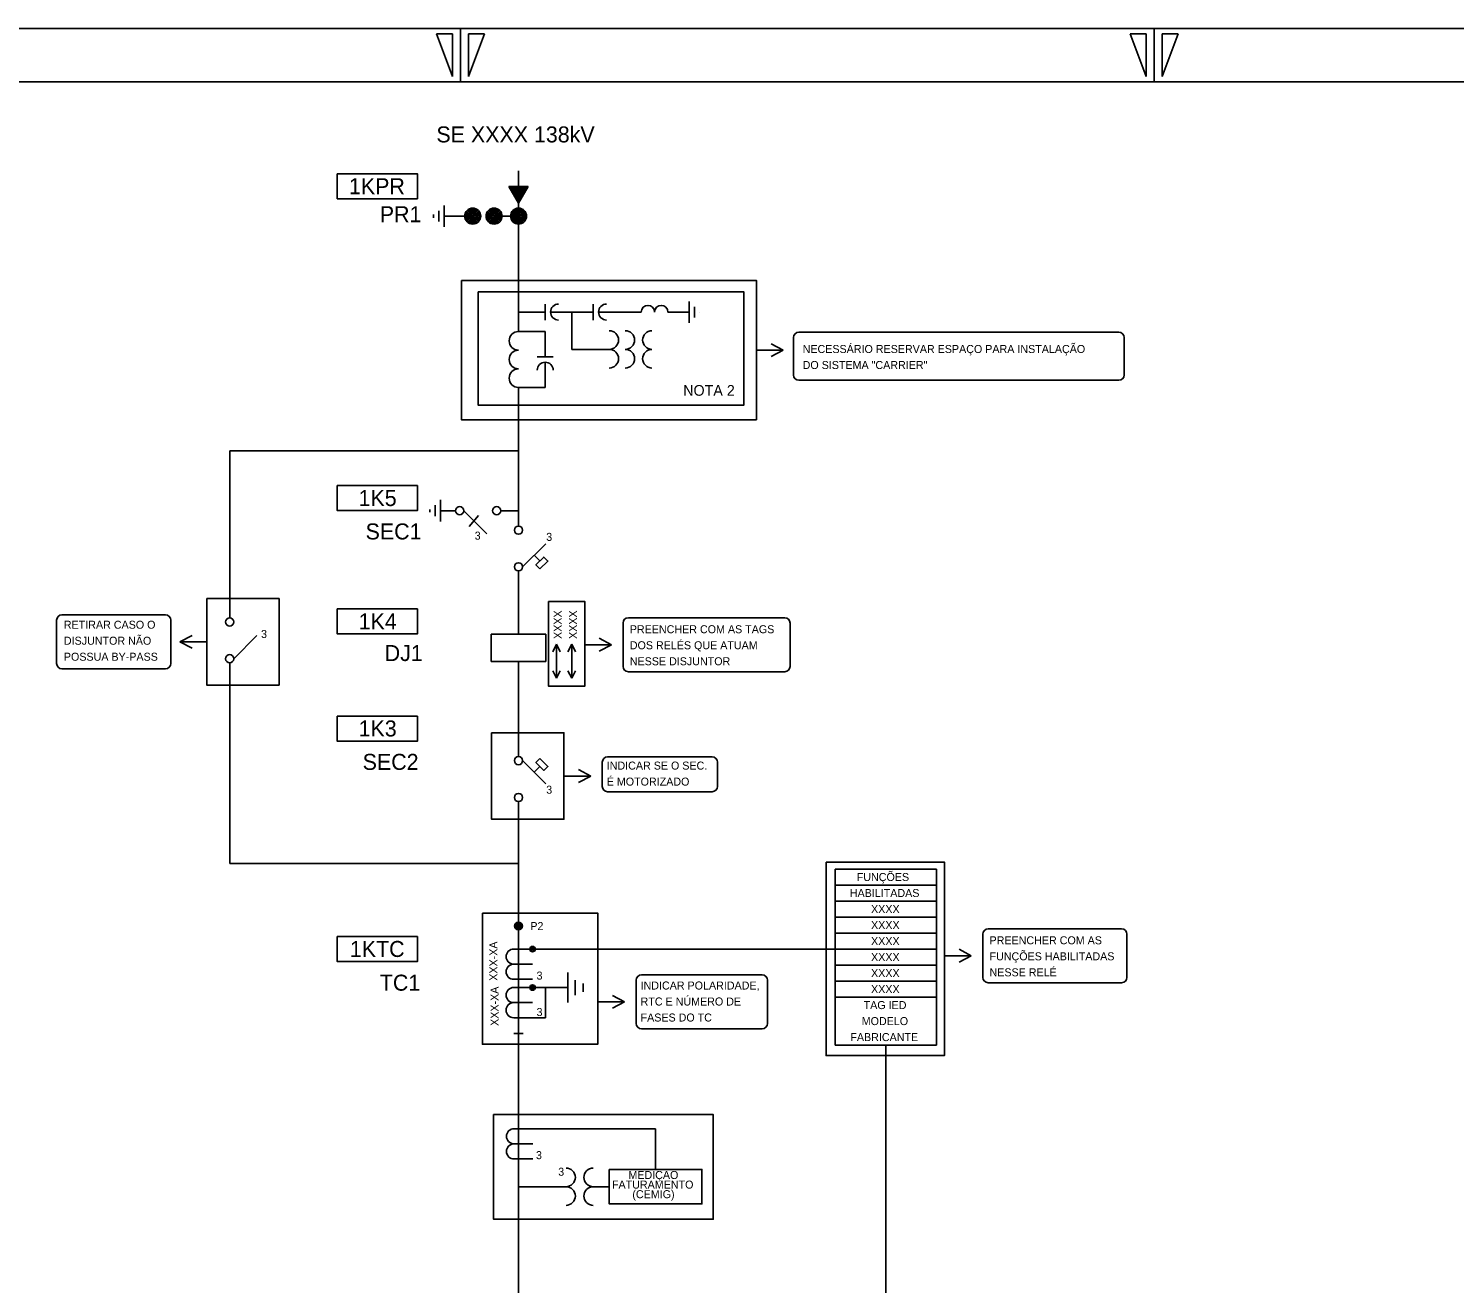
# Model space of a CAD drawing. Extents: x 563 to 1404, y 358 to 952.
# Drawn here: x 822.6 to 1089.8, y 716.8 to 952 of the extents above; entities that cross this region are included whole.
import ezdxf

# ---------------------------------------------------------------- set-up
doc = ezdxf.new("R2010")
doc.units = 0
doc.layers.add('Level 1', color=7, linetype='Continuous')
doc.layers.add('New Level (0)', color=7, linetype='Continuous')

msp = doc.modelspace()

# ---------------------------------------------------------------- linework, layer by layer
for p, q in [((914.46, 925.28), (914.46, 895.18)), ((916.27, 922.35), (912.65, 922.35)), ((912.65, 922.35), (914.46, 919.25)), ((916.27, 922.35), (912.65, 922.35)), ((916.08, 922.25), (912.83, 922.25)), ((912.83, 922.25), (914.46, 919.46)), ((915.9, 922.14), (913.01, 922.14)), ((913.01, 922.14), (914.46, 919.67)), ((915.72, 922.04), (913.19, 922.04)), ((913.19, 922.04), (914.46, 919.87)), ((915.54, 921.94), (913.37, 921.94)), ((913.37, 921.94), (914.46, 920.08)), ((914.46, 919.25), (916.27, 922.35)), ((914.46, 922.35), (914.46, 919.25)), ((914.46, 919.46), (916.08, 922.25)), ((914.46, 919.67), (915.9, 922.14)), ((914.46, 919.87), (915.72, 922.04)), ((914.46, 920.08), (915.54, 921.94)), ((915.36, 921.83), (913.55, 921.83)), ((913.55, 921.83), (914.46, 920.29)), ((915.18, 921.73), (913.73, 921.73)), ((913.73, 921.73), (914.46, 920.49)), ((915, 921.63), (913.91, 921.63)), ((913.91, 921.63), (914.46, 920.7)), ((914.82, 921.52), (914.09, 921.52)), ((914.09, 921.52), (914.46, 920.9)), ((914.64, 921.42), (914.27, 921.42)), ((914.27, 921.42), (914.46, 921.11)), ((914.46, 920.29), (915.36, 921.83)), ((914.46, 920.49), (915.18, 921.73)), ((914.46, 920.7), (915, 921.63)), ((914.46, 920.9), (914.82, 921.52)), ((914.46, 921.11), (914.64, 921.42)), ((898.55, 917.1), (898.55, 916.5)), ((898.55, 916.8), (898.55, 916.8)), ((899.55, 917.8), (899.55, 915.8)), ((900.55, 914.8), (900.55, 918.8)), ((901.87, 916.8), (900.55, 916.8)), ((905.87, 916.8), (901.87, 916.8)), ((914.46, 916.8), (909.87, 916.8)), ((914.46, 884.68), (914.46, 858.71)), ((914.46, 872.79), (860.34, 872.79)), ((860.34, 841.52), (860.34, 872.79)), ((899.86, 863.64), (899.86, 859.55)), ((897.82, 861.83), (897.82, 861.3)), ((898.83, 860.57), (898.83, 862.62)), ((902.65, 861.59), (899.86, 861.59)), ((908.52, 857.25), (904.18, 861.59)), ((905.18, 858.65), (906.97, 860.67)), ((914.46, 861.59), (911.13, 861.59)), ((919.56, 855.41), (915.22, 851.07)), ((918.45, 852.18), (917.39, 853.24)), ((914.46, 838.44), (914.46, 850.27)), ((865.45, 838.19), (861.11, 833.85)), ((909.34, 833.32), (909.34, 838.44)), ((909.34, 838.44), (919.58, 838.44)), ((919.58, 838.44), (919.58, 833.32)), ((921.57, 836.56), (920.86, 835.14)), ((921.57, 830.19), (921.57, 836.56)), ((921.57, 836.56), (922.28, 835.14)), ((924.42, 836.56), (923.71, 835.14)), ((924.42, 830.19), (924.42, 836.56)), ((924.42, 836.56), (925.13, 835.14)), ((860.34, 795.5), (860.34, 833.08)), ((919.58, 833.32), (909.34, 833.32)), ((914.46, 815.53), (914.46, 833.32)), ((921.57, 830.19), (920.86, 831.6)), ((921.57, 830.19), (922.28, 831.6)), ((924.42, 830.19), (923.71, 831.6)), ((924.42, 830.19), (925.13, 831.6)), ((919.56, 810.43), (915.22, 814.77)), ((918.45, 813.66), (917.39, 812.6)), ((914.46, 680.4), (914.46, 807.09)), ((914.46, 795.5), (860.34, 795.5)), ((992.76, 794.45), (973.77, 794.45)), ((973.77, 794.45), (973.77, 761.45)), ((992.76, 794.45), (992.76, 761.45)), ((992.76, 791.45), (973.77, 791.45)), ((992.76, 788.45), (973.77, 788.45)), ((992.76, 785.45), (973.77, 785.45)), ((992.76, 782.45), (973.77, 782.45)), ((913.55, 779.45), (917.09, 779.45)), ((917.09, 779.45), (973.77, 779.45)), ((992.76, 779.45), (973.77, 779.45)), ((913.55, 776.62), (917.09, 776.62)), ((923.7, 775.03), (923.7, 769.45)), ((992.76, 776.45), (973.77, 776.45)), ((992.76, 776.45), (973.77, 776.45)), ((913.55, 773.78), (917.09, 773.78)), ((913.55, 772.24), (917.09, 772.24)), ((915.32, 772.24), (923.7, 772.24)), ((925.09, 770.84), (925.09, 773.64)), ((926.57, 773.02), (926.57, 771.46)), ((992.76, 773.45), (973.77, 773.45)), ((992.76, 770.45), (973.77, 770.45)), ((913.55, 769.41), (917.09, 769.41)), ((913.55, 766.58), (919.51, 766.58)), ((992.76, 761.45), (973.77, 761.45)), ((913.61, 745.77), (917.15, 745.77)), ((917.15, 745.77), (940.14, 745.77)), ((913.61, 742.94), (917.15, 742.94)), ((913.61, 740.11), (917.15, 740.11)), ((914.52, 734.92), (923.36, 734.92)), ((928.46, 734.92), (931.46, 734.92))]:
    msp.add_line(p, q)
for points in [[(918.48, 850.68), (917.72, 851.45), (919.19, 852.92), (919.96, 852.15)], [(918.48, 815.16), (917.72, 814.39), (919.19, 812.92), (919.96, 813.69)]]:
    msp.add_lwpolyline(points, close=True)
for centre, radius in [((905.87, 916.8), 1.5), ((905.87, 916.8), 1.25), ((905.87, 916.8), 1), ((905.87, 916.8), 0.75), ((905.87, 916.8), 0.5), ((905.87, 916.8), 0.25), ((909.87, 916.8), 1.5), ((909.87, 916.8), 1.25), ((909.87, 916.8), 1), ((909.87, 916.8), 0.75), ((909.87, 916.8), 0.5), ((909.87, 916.8), 0.25), ((914.46, 916.8), 1.5), ((914.46, 916.8), 1.25), ((914.46, 916.8), 1), ((914.46, 916.8), 0.75), ((914.46, 916.8), 0.5), ((914.46, 916.8), 0.25), ((903.42, 861.59), 0.768), ((910.36, 861.59), 0.768), ((914.46, 857.94), 0.768), ((914.46, 851.07), 0.768), ((860.34, 840.75), 0.768), ((860.34, 833.85), 0.768), ((914.46, 814.77), 0.768), ((914.46, 807.86), 0.768), ((914.45, 783.78), 0.729), ((914.46, 783.78), 0.511), ((914.46, 783.78), 0.288), ((917.09, 779.44), 0.511), ((917.09, 779.44), 0.288), ((917.09, 772.24), 0.511), ((917.09, 772.24), 0.288)]:
    msp.add_circle(centre, radius)
for centre, radius, start, end in [((913.55, 778.03), 1.42, 90, 270), ((913.55, 775.2), 1.42, 90, 270), ((913.55, 770.83), 1.42, 90, 270), ((913.55, 768), 1.42, 90, 270), ((913.61, 744.36), 1.42, 90, 270), ((913.61, 741.53), 1.42, 90, 270), ((923.36, 736.67), 1.75, 270, 90), ((928.46, 736.67), 1.75, 90, 270), ((923.36, 733.17), 1.75, 270, 90), ((928.46, 733.17), 1.75, 90, 270)]:
    msp.add_arc(centre, radius, start, end)
at = {"layer": 'Level 1'}
for p, q in [((946.46, 900.83), (946.46, 896.83)), ((914.46, 898.83), (919.46, 898.83)), ((919.46, 900.33), (919.46, 897.33)), ((920.46, 898.83), (928.46, 898.83)), ((924.46, 898.83), (924.46, 891.83)), ((928.46, 900.33), (928.46, 897.33)), ((929.46, 898.83), (937.46, 898.83)), ((942.46, 898.83), (946.46, 898.83)), ((947.46, 897.83), (947.46, 899.83)), ((948.46, 898.83), (948.46, 898.83)), ((919.46, 895.18), (914.46, 895.18)), ((919.46, 890.43), (919.46, 895.18)), ((917.96, 890.43), (920.96, 890.43)), ((924.46, 891.83), (931.46, 891.83)), ((919.46, 884.68), (919.46, 889.43)), ((914.46, 884.68), (919.46, 884.68))]:
    msp.add_line(p, q, dxfattribs=at)
for centre, radius, start, end in [((921.96, 898.83), 1.5, 90, 270), ((930.96, 898.83), 1.5, 90, 270), ((938.71, 898.83), 1.25, 0, 180), ((941.21, 898.83), 1.25, 0, 180), ((914.46, 893.43), 1.75, 90, 270), ((931.46, 893.58), 1.75, 270, 90), ((934.46, 893.58), 1.75, 270, 90), ((939.46, 893.58), 1.75, 90, 270), ((914.46, 889.93), 1.75, 90, 270), ((931.46, 890.08), 1.75, 270, 90), ((934.46, 890.08), 1.75, 270, 90), ((939.46, 890.08), 1.75, 90, 270), ((914.46, 886.43), 1.75, 90, 270), ((919.46, 887.93), 1.5, 0, 180)]:
    msp.add_arc(centre, radius, start, end, dxfattribs=at)
at = {"layer": 'New Level (0)'}
for p, q in [((1403.58, 951.96), (562.58, 951.96)), ((1403.58, 951.96), (562.58, 951.96)), ((903.58, 951.96), (903.58, 941.96)), ((1033.58, 951.96), (1033.58, 941.96)), ((902.08, 950.96), (899.08, 950.96)), ((899.08, 950.96), (902.08, 942.96)), ((902.08, 942.96), (902.08, 950.96)), ((905.08, 942.96), (905.08, 950.96)), ((905.08, 950.96), (908.08, 950.96)), ((908.08, 950.96), (905.08, 942.96)), ((1032.08, 950.96), (1029.08, 950.96)), ((1029.08, 950.96), (1032.08, 942.96)), ((1032.08, 942.96), (1032.08, 950.96)), ((1035.08, 942.96), (1035.08, 950.96)), ((1035.08, 950.96), (1038.08, 950.96)), ((1038.08, 950.96), (1035.08, 942.96)), ((1393.58, 941.96), (572.58, 941.96)), ((964.08, 891.68), (961.78, 892.89)), ((965.99, 887.03), (965.99, 894.06)), ((966.99, 895.06), (997.07, 895.06)), ((997.07, 895.06), (1026.95, 895.06)), ((1027.95, 894.06), (1027.95, 887.03)), ((959.05, 891.68), (964.08, 891.68)), ((964.08, 891.68), (961.78, 890.48)), ((1026.95, 886.03), (966.99, 886.03)), ((828.91, 842.08), (832.67, 842.08)), ((832.67, 842.08), (848.31, 842.08)), ((827.91, 832.96), (827.91, 841.08)), ((849.31, 841.08), (849.31, 832.96)), ((934.05, 832.43), (934.05, 840.54)), ((935.05, 841.54), (942.4, 841.54)), ((942.4, 841.54), (964.34, 841.54)), ((965.34, 840.54), (965.34, 832.43)), ((851.01, 837.02), (853.31, 838.23)), ((856.04, 837.02), (851.01, 837.02)), ((851.01, 837.02), (853.31, 835.81)), ((926.86, 836.48), (931.89, 836.48)), ((931.89, 836.48), (929.59, 837.69)), ((931.89, 836.48), (929.59, 835.27)), ((848.31, 831.96), (828.91, 831.96)), ((964.34, 831.43), (935.05, 831.43)), ((931.16, 815.48), (938.51, 815.48)), ((938.51, 815.48), (950.74, 815.48)), ((928, 811.88), (925.7, 813.09)), ((930.16, 809.93), (930.16, 814.48)), ((951.74, 814.48), (951.74, 809.93)), ((922.97, 811.88), (928, 811.88)), ((928, 811.88), (925.7, 810.67)), ((950.74, 808.93), (931.16, 808.93)), ((1002.46, 783.25), (1009.81, 783.25)), ((1009.81, 783.25), (1027.47, 783.25)), ((1001.46, 774.14), (1001.46, 782.25)), ((1028.47, 782.25), (1028.47, 774.14)), ((994.27, 778.19), (999.3, 778.19)), ((999.3, 778.19), (997, 779.4)), ((999.3, 778.19), (997, 776.98)), ((919.51, 772.24), (919.51, 766.58)), ((936.5, 765.51), (936.5, 773.62)), ((937.5, 774.62), (944.85, 774.62)), ((944.85, 774.62), (960.11, 774.62)), ((961.11, 773.62), (961.11, 765.51)), ((1027.47, 773.14), (1002.46, 773.14)), ((929.31, 769.57), (934.34, 769.57)), ((934.34, 769.57), (932.04, 770.77)), ((934.34, 769.57), (932.04, 768.36)), ((960.11, 764.51), (937.5, 764.51)), ((913.56, 763.63), (915.36, 763.63)), ((983.27, 761.45), (983.27, 703.79)), ((940.14, 738.16), (940.14, 745.77))]:
    msp.add_line(p, q, dxfattribs=at)
for points in [[(880.5, 924.73), (895.52, 924.73), (895.52, 920.04), (880.5, 920.04)], [(903.77, 904.74), (959.05, 904.74), (959.05, 878.63), (903.77, 878.63)], [(906.91, 902.64), (956.67, 902.64), (956.67, 881.36), (906.91, 881.36)], [(880.5, 866.29), (895.52, 866.29), (895.52, 861.61), (880.5, 861.61)], [(856.04, 845.13), (869.6, 845.13), (869.6, 828.91), (856.04, 828.91)], [(920.08, 844.59), (926.86, 844.59), (926.86, 828.7), (920.08, 828.7)], [(880.5, 843.19), (895.52, 843.19), (895.52, 838.5), (880.5, 838.5)], [(880.5, 823.09), (895.52, 823.09), (895.52, 818.4), (880.5, 818.4)], [(909.41, 819.99), (922.97, 819.99), (922.97, 803.77), (909.41, 803.77)], [(972.08, 795.75), (994.27, 795.75), (994.27, 759.49), (972.08, 759.49)], [(907.69, 786.18), (929.31, 786.18), (929.31, 761.61), (907.69, 761.61)], [(880.5, 781.78), (895.52, 781.78), (895.52, 777.1), (880.5, 777.1)], [(909.78, 748.44), (950.94, 748.44), (950.94, 728.83), (909.78, 728.83)], [(931.46, 738.16), (948.81, 738.16), (948.81, 731.69), (931.46, 731.69)]]:
    msp.add_lwpolyline(points, close=True, dxfattribs=at)
for centre, start, end in [((966.99, 894.06), 90, 180), ((1026.95, 894.06), 0, 90), ((966.99, 887.03), 180, 270), ((1026.95, 887.03), 270, 0), ((828.91, 841.08), 90, 180), ((848.31, 841.08), 0, 90), ((935.05, 840.54), 90, 180), ((964.34, 840.54), 0, 90), ((828.91, 832.96), 180, 270), ((848.31, 832.96), 270, 0), ((935.05, 832.43), 180, 270), ((964.34, 832.43), 270, 0), ((931.16, 814.48), 90, 180), ((950.74, 814.48), 0, 90), ((931.16, 809.93), 180, 270), ((950.74, 809.93), 270, 0), ((1002.46, 782.25), 90, 180), ((1027.47, 782.25), 0, 90), ((937.5, 773.62), 90, 180), ((960.11, 773.62), 0, 90), ((1002.46, 774.14), 180, 270), ((1027.47, 774.14), 270, 0), ((937.5, 765.51), 180, 270), ((960.11, 765.51), 270, 0)]:
    msp.add_arc(centre, 1, start, end, dxfattribs=at)

# ---------------------------------------------------------------- texts
for s, height, p in [('SE XXXX 138kV', 3, (899.07, 930.61)), ('1KPR', 3, (882.68, 920.91)), ('PR1', 3, (888.46, 915.66)), ('NECESSÁRIO RESERVAR ESPAÇO PARA INSTALAÇÃO ', 1.5, (967.7, 891.15)), ('DO SISTEMA "CARRIER"', 1.5, (967.7, 888.15)), ('NOTA 2', 2, (945.32, 883.14)), ('1K5', 3, (884.48, 862.47)), ('SEC1', 3, (885.8, 856.21)), ('3', 1.5, (906.24, 856.17)), ('3', 1.5, (919.65, 855.94)), ('1K4', 3, (884.5, 839.36)), ('RETIRAR CASO O ', 1.5, (829.26, 839.48)), ('3', 1.5, (866.21, 837.74)), ('PREENCHER COM AS TAGS ', 1.5, (935.31, 838.63)), ('DISJUNTOR NÃO ', 1.5, (829.26, 836.48)), ('DJ1', 3, (889.38, 833.42)), ('DOS RELÉS QUE ATUAM ', 1.5, (935.31, 835.63)), ('POSSUA BY-PASS', 1.5, (829.26, 833.48)), ('NESSE DISJUNTOR', 1.5, (935.31, 832.63)), ('1K3', 3, (884.49, 819.29)), ('SEC2', 3, (885.25, 813.03)), ('INDICAR SE O SEC. ', 1.5, (930.99, 813.08)), ('3', 1.5, (919.65, 808.56)), ('É MOTORIZADO', 1.5, (930.99, 810.08)), ('FUNÇÕES ', 1.5, (977.84, 792.2)), ('HABILITADAS', 1.5, (976.54, 789.2)), ('XXXX', 1.5, (980.52, 786.2)), ('P2', 1.5, (916.67, 783.01)), ('XXXX', 1.5, (980.52, 783.2)), ('1KTC', 3, (882.85, 777.97)), ('XXXX', 1.5, (980.52, 780.2)), ('PREENCHER COM AS ', 1.5, (1002.72, 780.34)), ('XXXX', 1.5, (980.52, 777.2)), ('FUNÇÕES HABILITADAS ', 1.5, (1002.72, 777.34)), ('3', 1.5, (917.84, 773.73)), ('XXXX', 1.5, (980.52, 774.2)), ('NESSE RELÉ', 1.5, (1002.72, 774.34)), ('TC1', 3, (888.47, 771.65)), ('INDICAR POLARIDADE, ', 1.5, (937.33, 771.87)), ('XXXX', 1.5, (980.52, 771.2)), ('RTC E NÚMERO DE ', 1.5, (937.33, 768.87)), ('TAG IED', 1.5, (979.13, 768.2)), ('3', 1.5, (917.84, 766.9)), ('FASES DO TC', 1.5, (937.33, 765.87)), ('MODELO', 1.5, (978.77, 765.2)), ('FABRICANTE', 1.5, (976.64, 762.2)), ('3', 1.5, (917.73, 740.08)), ('3', 1.5, (921.9, 736.97)), ('MEDIÇÃO', 1.5, (935.05, 736.36)), ('FATURAMENTO', 1.5, (931.97, 734.56)), ('(CEMIG)', 1.5, (935.79, 732.76))]:
    msp.add_text(s, height=height).set_placement(p)
for s, p in [('XXXX', (922.57, 837.56)), ('XXXX', (925.42, 837.56)), ('XXX-XA', (910.51, 773.51)), ('XXX-XA', (910.71, 765.05))]:
    msp.add_text(s, height=1.5, rotation=90).set_placement(p)

doc.saveas('drawing.dxf')
